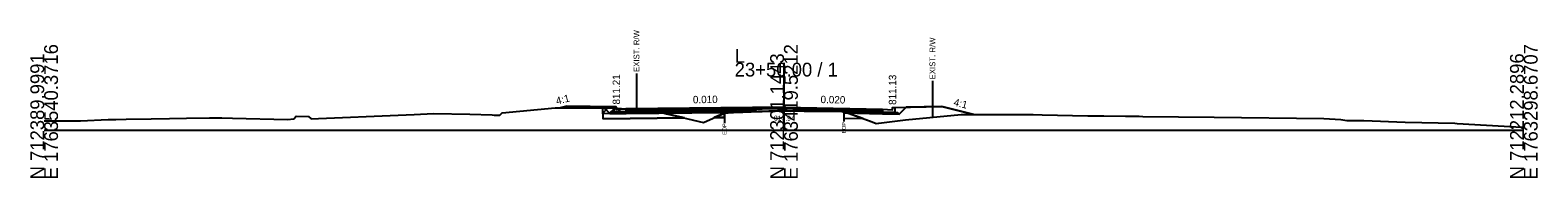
# Model space of a CAD drawing. Extents: x -26 to 5303, y -10 to 9578.
# Drawn here: x 997.2 to 1302.8, y 3490.3 to 3520.3 of the extents above; entities that cross this region are included whole.
import ezdxf

# ---------------------------------------------------------------- set-up
doc = ezdxf.new("R2010")
doc.units = 0
for name, color, linetype in [('Default', 7, 'Continuous'), ('Exist CMT Pavement', 7, 'Continuous'), ('Exist Cross Section Cell', 7, 'Continuous'), ('Exist XS Ground Line', 7, 'Continuous'), ('Old_Level_10', 7, 'Continuous'), ('Old_Level_3', 7, 'Continuous'), ('Prop CMT Conc Surface', 7, 'Continuous'), ('Prop CMT Concrete Structures', 7, 'Continuous'), ('Prop CMT Pvmt Course 1', 7, 'Continuous'), ('Prop CMT Pvmt Course 1 CG', 7, 'Continuous'), ('Prop CMT Pvmt Course 2', 7, 'Continuous'), ('Prop CMT Pvmt Course 3', 7, 'Continuous'), ('Prop CMT Pvmt Surface', 7, 'Continuous'), ('Prop CMT Slope Grass', 7, 'Continuous'), ('Prop CMT Subgrade Earthwork', 7, 'Continuous'), ('Prop Shade Light', 7, 'Continuous'), ('Prop XS Earthwork Shape', 7, 'Continuous'), ('Prop XS Hydro Elevations', 7, 'Continuous'), ('Prop XS SE Text', 7, 'Continuous'), ('Prop XS Side Slope Text', 7, 'Continuous'), ('Prop XS Wedging', 7, 'Continuous'), ('Scratch_Level_5', 7, 'Continuous')]:
    doc.layers.add(name, color=color, linetype=linetype)

msp = doc.modelspace()

# ---------------------------------------------------------------- linework, layer by layer
at = {"layer": 'Exist CMT Pavement'}
msp.add_lwpolyline([(1137.93, 3503.5), (1137.93, 3503.5), (1138.68, 3503.54), (1139.75, 3503.59), (1141.65, 3503.64), (1143.32, 3503.71), (1144.75, 3503.79), (1145.11, 3503.8), (1145.6, 3503.82), (1146.9, 3503.86), (1147.85, 3503.89), (1148.69, 3503.92), (1149.2, 3503.93), (1149.52, 3503.94), (1150.23, 3503.94), (1150.67, 3503.91), (1151.28, 3503.89), (1151.79, 3503.9), (1152.26, 3503.9), (1154.06, 3503.89), (1155.84, 3503.87), (1157.16, 3503.87), (1157.63, 3503.87), (1158.26, 3503.86), (1159.42, 3503.86), (1160.27, 3503.85), (1161.21, 3503.83), (1161.71, 3503.82), (1162.14, 3503.79)], dxfattribs=at)
at = {"layer": 'Exist Cross Section Cell'}
for p, q in [((1150, 3500), (1150, 3513.7)), ((1000, 3500), (1150, 3500)), ((1150, 3500), (1300, 3500))]:
    msp.add_line(p, q, dxfattribs=at)
at = {"layer": 'Exist XS Ground Line'}
msp.add_lwpolyline([(1000, 3501.87), (1000.56, 3501.88), (1007.37, 3501.89), (1012.97, 3502.15), (1014.53, 3502.2), (1016.64, 3502.23), (1021.68, 3502.33), (1025.38, 3502.39), (1028.83, 3502.45), (1033.53, 3502.5), (1035.99, 3502.52), (1038.2, 3502.46), (1049.33, 3502.2), (1050.64, 3502.33), (1051.09, 3502.83), (1053.6, 3502.8), (1054.1, 3502.3), (1055.61, 3502.37), (1071.76, 3503.04), (1075.04, 3503.2), (1078.91, 3503.36), (1086.27, 3503.22), (1090.86, 3503.1), (1091.23, 3503.08), (1092.36, 3503.03), (1092.86, 3503.53), (1103.57, 3504.55), (1112.93, 3504.57), (1116.28, 3504.45), (1124.96, 3503.69), (1126.2, 3503.33), (1133.71, 3501.58), (1137.45, 3503.27), (1137.93, 3503.5), (1138.68, 3503.54), (1139.75, 3503.59), (1141.65, 3503.64), (1143.32, 3503.71), (1144.75, 3503.79), (1145.11, 3503.8), (1145.6, 3503.82), (1147.85, 3503.89), (1148.69, 3503.92), (1149.3, 3503.93), (1150.23, 3503.94), (1151.28, 3503.89), (1151.79, 3503.9), (1152.26, 3503.9), (1154.06, 3503.89), (1155.84, 3503.87), (1157.16, 3503.87), (1157.63, 3503.87), (1158.26, 3503.86), (1160.27, 3503.85), (1161.21, 3503.83), (1161.71, 3503.82), (1162.14, 3503.79), (1167.87, 3501.68), (1168.7, 3501.37), (1169.24, 3501.45), (1174.62, 3502.1), (1185.91, 3503.17), (1186.22, 3503.21), (1186.76, 3503.2), (1193.37, 3503.16), (1199.17, 3503.18), (1200.53, 3503.18), (1202.36, 3503.1), (1211.59, 3502.9), (1214.83, 3502.93), (1219.25, 3502.84), (1221.99, 3502.86), (1222.72, 3502.8), (1237.21, 3502.64), (1259.48, 3502.37), (1262.87, 3502.2), (1264.09, 3501.98), (1267.55, 3501.98), (1275.96, 3501.66), (1286.03, 3501.4), (1286.45, 3501.38), (1298.37, 3500.67), (1300, 3500.6)], dxfattribs=at)
at = {"layer": 'Old_Level_10'}
for p, q in [((1120.09, 3511.52), (1120.09, 3504.11)), ((1180.09, 3510.02), (1180.09, 3502.62)), ((1137.93, 3503.5), (1137.93, 3501.45)), ((1162.14, 3503.79), (1162.14, 3501.74))]:
    msp.add_line(p, q, dxfattribs=at)
at = {"layer": 'Prop CMT Conc Surface'}
for points in [[(1116, 3504.21), (1116, 3504.71), (1115.5, 3504.71)], [(1118, 3504.32), (1116, 3504.21)], [(1170, 3504.25), (1172, 3504.13)], [(1172, 3504.13), (1172, 3504.63), (1172.5, 3504.63)]]:
    msp.add_lwpolyline(points, dxfattribs=at)
at = {"layer": 'Prop CMT Concrete Structures'}
for points in [[(1118, 3504.32), (1116, 3504.21), (1116, 3504.71), (1115.5, 3504.71)], [(1115.5, 3504.71), (1115.5, 3503.71), (1118, 3503.73)], [(1118, 3503.73), (1118, 3504.32)], [(1170, 3504.25), (1172, 3504.13), (1172, 3504.63), (1172.5, 3504.63)], [(1172.5, 3504.63), (1172.5, 3503.61), (1170, 3503.66)], [(1170, 3503.66), (1170, 3504.25)]]:
    msp.add_lwpolyline(points, dxfattribs=at)
at = {"layer": 'Prop CMT Pvmt Course 1'}
for points in [[(1150, 3504.65), (1118, 3504.32)], [(1118, 3504.32), (1118, 3504.07)], [(1118, 3504.07), (1137.93, 3504.27)], [(1137.93, 3504.27), (1150, 3504.4)], [(1137.93, 3504.27), (1137.93, 3504.27)], [(1150, 3504.4), (1150, 3504.65)], [(1150, 3504.65), (1170, 3504.25)], [(1150, 3504.4), (1150, 3504.4), (1150, 3504.4)], [(1162.14, 3504.15), (1150, 3504.4)], [(1170, 3504), (1162.14, 3504.15)], [(1162.14, 3504.15), (1162.14, 3504.15)], [(1170, 3504.25), (1170, 3504)]]:
    msp.add_lwpolyline(points, dxfattribs=at)
at = {"layer": 'Prop CMT Pvmt Course 1 CG'}
for points in [[(1118, 3503.73), (1115, 3503.7), (1114.66, 3503.36)], [(1114.66, 3503.36), (1118, 3503.4)], [(1118, 3503.4), (1118, 3503.73)], [(1170, 3503.66), (1173, 3503.6), (1173.34, 3503.26)], [(1170, 3503.33), (1170, 3503.66)], [(1173.34, 3503.26), (1170, 3503.33)]]:
    msp.add_lwpolyline(points, dxfattribs=at)
at = {"layer": 'Prop CMT Pvmt Course 2'}
for points in [[(1137.93, 3504.27), (1118, 3504.07)], [(1118, 3504.07), (1118, 3503.73)], [(1118, 3503.73), (1137.93, 3503.94)], [(1137.93, 3503.94), (1137.93, 3504.27)], [(1162.14, 3503.82), (1162.14, 3504.15)], [(1162.14, 3504.15), (1170, 3504)], [(1170, 3503.66), (1162.14, 3503.82)], [(1170, 3504), (1170, 3503.66)]]:
    msp.add_lwpolyline(points, dxfattribs=at)
at = {"layer": 'Prop CMT Pvmt Course 3'}
for points in [[(1137.93, 3503.94), (1118, 3503.73)], [(1118, 3503.73), (1118, 3503.4)], [(1118, 3503.4), (1137.93, 3503.61)], [(1137.93, 3503.61), (1137.93, 3503.94)], [(1162.14, 3503.82), (1170, 3503.66)], [(1162.14, 3503.49), (1162.14, 3503.82)], [(1170, 3503.33), (1162.14, 3503.49)], [(1170, 3503.66), (1170, 3503.33)]]:
    msp.add_lwpolyline(points, dxfattribs=at)
at = {"layer": 'Prop CMT Pvmt Surface'}
for points in [[(1150, 3504.65), (1118, 3504.32)], [(1150, 3504.65), (1170, 3504.25)]]:
    msp.add_lwpolyline(points, dxfattribs=at)
at = {"layer": 'Prop CMT Slope Grass'}
for points in [[(1115.5, 3504.71), (1106, 3504.9), (1104.59, 3504.55)], [(1172.5, 3504.63), (1182, 3504.82), (1188.51, 3503.19)]]:
    msp.add_lwpolyline(points, dxfattribs=at)
at = {"layer": 'Prop CMT Subgrade Earthwork'}
for p, q in [((1137.93, 3503.61), (1137.93, 3503.5)), ((1162.14, 3503.49), (1162.14, 3503.79))]:
    msp.add_line(p, q, dxfattribs=at)
for points in [[(1118, 3503.4), (1114.66, 3503.36), (1113.27, 3504.76)], [(1162.14, 3503.49), (1170, 3503.33)], [(1170, 3503.33), (1173.34, 3503.26), (1174.75, 3504.67)]]:
    msp.add_lwpolyline(points, dxfattribs=at)
at = {"layer": 'Prop Shade Light'}
for p, q in [((1114.66, 3503.36), (1113.27, 3503.35)), ((1113.27, 3503.35), (1113.27, 3502.31)), ((1113.27, 3503.35), (1113.27, 3502.31)), ((1125.69, 3503.48), (1118, 3503.4)), ((1137.93, 3503.61), (1137.93, 3502.57)), ((1137.93, 3502.57), (1137.93, 3503.5)), ((1162.14, 3503.49), (1162.14, 3502.45)), ((1162.14, 3503.49), (1162.14, 3502.45)), ((1163, 3503.47), (1162.14, 3503.49)), ((1165.99, 3502.37), (1163, 3503.47)), ((1113.27, 3502.31), (1129.84, 3502.48)), ((1135.84, 3502.55), (1137.93, 3502.57)), ((1162.14, 3502.45), (1165.99, 3502.37))]:
    msp.add_line(p, q, dxfattribs=at)
for points in [[(1118, 3503.4), (1113.27, 3503.35)], [(1118, 3503.4), (1114.66, 3503.36), (1114.66, 3503.36)], [(1129.84, 3502.48), (1126.2, 3503.33), (1125.69, 3503.48)], [(1137.93, 3503.5), (1137.45, 3503.27), (1135.84, 3502.55)], [(1129.84, 3502.48), (1113.27, 3502.31)], [(1137.93, 3502.57), (1135.84, 3502.55)], [(1162.14, 3502.45), (1165.99, 3502.37)]]:
    msp.add_lwpolyline(points, dxfattribs=at)
at = {"layer": 'Prop XS Earthwork Shape'}
for points in [[(1113.27, 3504.76), (1106, 3504.9), (1104.59, 3504.55), (1112.93, 3504.57), (1113.48, 3504.55)], [(1114.66, 3503.36), (1113.48, 3504.55), (1116, 3504.46), (1116, 3504.21), (1117.87, 3504.31), (1124.96, 3503.69), (1125.69, 3503.48), (1118, 3503.4)], [(1116, 3504.21), (1116, 3504.46), (1116.28, 3504.45), (1117.87, 3504.31)], [(1137.45, 3503.27), (1137.93, 3503.5), (1137.93, 3503.61), (1125.69, 3503.48), (1126.2, 3503.33), (1133.71, 3501.58)], [(1162.14, 3503.49), (1163, 3503.47), (1162.14, 3503.79)], [(1185.91, 3503.17), (1186.22, 3503.21), (1186.76, 3503.2), (1188.51, 3503.19), (1182, 3504.82), (1174.75, 3504.67), (1173.34, 3503.26), (1170, 3503.33), (1163, 3503.47), (1167.87, 3501.68), (1168.7, 3501.37), (1169.24, 3501.45), (1174.62, 3502.1)]]:
    msp.add_lwpolyline(points, close=True, dxfattribs=at)
at = {"layer": 'Prop XS Wedging'}
for points in [[(1137.92, 3503.5), (1137.92, 3504.27), (1138.68, 3504.28), (1139.75, 3504.29), (1141.65, 3504.31), (1143.32, 3504.33), (1144.75, 3504.34), (1145.11, 3504.35), (1145.6, 3504.35), (1146.9, 3504.37), (1147.85, 3504.38), (1148.69, 3504.38), (1149.19, 3504.39), (1149.52, 3504.39), (1150, 3504.4), (1150.23, 3504.39), (1150.67, 3504.38), (1151.28, 3504.37), (1151.79, 3504.36), (1152.26, 3504.35), (1154.06, 3504.32), (1155.84, 3504.28), (1157.16, 3504.25), (1157.63, 3504.25), (1158.26, 3504.23), (1159.42, 3504.21), (1160.27, 3504.19), (1161.2, 3504.17), (1161.71, 3504.16), (1162.14, 3504.16), (1162.14, 3503.79), (1161.71, 3503.82), (1161.2, 3503.83), (1160.27, 3503.85), (1159.42, 3503.86), (1158.26, 3503.87), (1157.63, 3503.87), (1157.16, 3503.87), (1155.84, 3503.87), (1154.06, 3503.89), (1152.26, 3503.9), (1151.79, 3503.9), (1151.28, 3503.89), (1150.67, 3503.91), (1150.23, 3503.94), (1150, 3503.94), (1149.52, 3503.93), (1149.19, 3503.93), (1148.69, 3503.92), (1147.85, 3503.89), (1146.9, 3503.86), (1145.6, 3503.82), (1145.11, 3503.8), (1144.75, 3503.79), (1143.32, 3503.71), (1141.65, 3503.64), (1139.75, 3503.59), (1138.68, 3503.54)], [(1137.92, 3503.5), (1137.92, 3503.94), (1138.68, 3503.95), (1139.75, 3503.96), (1141.65, 3503.98), (1143.32, 3504), (1144.24, 3504.01), (1144.48, 3503.77), (1143.32, 3503.71), (1141.65, 3503.64), (1139.75, 3503.59), (1138.68, 3503.54)]]:
    msp.add_lwpolyline(points, close=True, dxfattribs=at)
at = {"layer": 'Scratch_Level_5'}
for p, q in [((1113.27, 3503.35), (1113.27, 3504.57)), ((1113.27, 3503.47), (1114.31, 3504.52)), ((1114.57, 3503.36), (1115.68, 3504.47)), ((1116, 3503.38), (1117.01, 3504.38)), ((1117.43, 3503.39), (1118.31, 3504.27)), ((1118.86, 3503.41), (1119.61, 3504.16)), ((1120.29, 3503.42), (1120.91, 3504.04)), ((1121.72, 3503.44), (1122.21, 3503.93)), ((1123.15, 3503.45), (1123.51, 3503.82)), ((1124.58, 3503.47), (1124.81, 3503.7))]:
    msp.add_line(p, q, dxfattribs=at)

# ---------------------------------------------------------------- texts
at = {"layer": 'Default'}
msp.add_text('-', height=0.0001, dxfattribs=at).set_placement((1000, 3500))
at = {"layer": 'Exist Cross Section Cell'}
for s, p in [('N 712389.9991', (1000, 3490)), ('E 1763540.3716', (1002.8, 3490)), ('N 712301.1443', (1150, 3490)), ('E 1763419.5212', (1152.8, 3490)), ('N 712212.2896', (1300, 3490)), ('E 1763298.6707', (1302.8, 3490))]:
    msp.add_text(s, height=2.8, rotation=90, dxfattribs=at).set_placement(p)
for s, p in [('L', (1140, 3513.7)), ('23+50.00 / 1', (1140, 3510.9))]:
    msp.add_text(s, height=2.8, dxfattribs=at).set_placement(p)
at = {"layer": 'Old_Level_10'}
for s, height, p in [('EXIST. R/W', 1.181, (1120.68, 3511.82)), ('EXIST. R/W', 1.181, (1180.68, 3510.32)), ('EOP', 0.787, (1138.32, 3499.06)), ('EOP', 0.787, (1162.53, 3499.34))]:
    msp.add_text(s, height=height, rotation=90, dxfattribs=at).set_placement(p)
at = {"layer": 'Old_Level_3'}
msp.add_text('810.94', height=1, dxfattribs=at).set_placement((1147.95, 3501.94))
at = {"layer": 'Prop XS Hydro Elevations'}
for s, p in [('811.21', (1116.75, 3505.21)), ('811.13', (1172.75, 3505.13))]:
    msp.add_text(s, height=1.5, rotation=90, dxfattribs=at).set_placement(p)
at = {"layer": 'Prop XS SE Text'}
for s, rotation, p in [('0.010', 0.5943, (1131.54, 3505.46)), ('0.020', 358.8542, (1157.4, 3505.5))]:
    msp.add_text(s, height=1.5, rotation=rotation, dxfattribs=at).set_placement(p)
at = {"layer": 'Prop XS Side Slope Text'}
for rotation, p in [(14.0362, (1103.96, 3505.17)), (345.9638, (1184.28, 3505.02))]:
    msp.add_text('4:1', height=1.5, rotation=rotation, dxfattribs=at).set_placement(p)

doc.saveas('drawing.dxf')
